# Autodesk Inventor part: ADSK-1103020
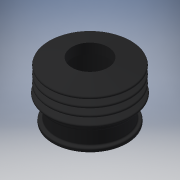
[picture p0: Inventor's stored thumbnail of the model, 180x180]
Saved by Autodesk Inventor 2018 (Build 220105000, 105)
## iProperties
Shininess: 50.0
Length Units: 11272
Angle Units: 11279
Time Units: 11290
Mass Units: 11286
Length Display Precision: 4
Angle Display Precision: 2
Compacted: True
Created: 2000-09
Part Number: ADSK-1103020
Document SubType Name: Modeling
Description: DUST BOOT
Mass: 0.811722 g
Surface Area: 17.5384 cm^2
Volume: 0.872819 cm^3
Density: 0.93 g/cm^3
Material: Rubber
Appearance: Black
Density: 0.0
Volumn: 0.0
Area: 0.0
PropertySet Name: Model Information
Control State: 0
Master: False
Checked Out: False
Author: Autodesk, Inc.
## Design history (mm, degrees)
sketch "Sketch2"
  geometry: L1 (-7.556, -0.987)-(-7.555, -2.302); L2 (-7.428, -0.26)-(-12.947, -1.655); L3 (-3.726, 0)-(-3.726, -10.16); L4 (-9.439, -1.463)-(-7.556, -0.987); L5 (-6.708, -0.987)-(-6.708, -0.26); L6 (-6.708, -0.987)-(-6.708, -2.302); L7 (-6.708, -2.302)-(-7.555, -2.302); L8 (-6.708, -0.26)-(-7.428, -0.26); L9 (-10.074, -10.258)-(-8.804, -10.257); L10 (-8.804, -10.257)-(-8.806, -7.743); L11 (-8.806, -7.743)-(-9.432, -7.744); L12 (-9.432, -7.744)-(-9.439, -1.463); L13 (-10.074, -10.258)-(-10.072, -11.94); L14 (-10.072, -11.94)-(-11.389, -11.941); L15 (-11.389, -11.941)-(-11.389, -11.14); L16 (-11.389, -11.14)-(-10.659, -11.14); L17 (-10.659, -11.14)-(-10.662, -8.05); L18 (-10.662, -8.05)-(-11.393, -8.051); L19 (-12.947, -1.655)-(-9.718, -2.471); L20 (-9.718, -2.471)-(-12.947, -3.287); L21 (-12.947, -3.287)-(-9.718, -4.103); L22 (-9.718, -4.103)-(-12.947, -4.919); L23 (-12.947, -4.919)-(-9.718, -5.735); L24 (-9.718, -5.735)-(-12.947, -6.551); L25 (-12.947, -6.551)-(-11.394, -7.099); L26 (-11.393, -8.051)-(-11.394, -7.099); L27 (-11.395, -6.159)-(-11.395, -6.146)
  constraints: 54 end point, 15 parallel, 4 perpendicular, 1 collinear, 1 point on line
workaxis "Work Axis1"
node "Revolution1" dims "d0" = 90 deg
node "Fillet1" dims "d1" = 0.254
sketch "Sketch4"
  geometry: C1 r 2.981 at (3.726, 0) reference; C2 r 3.701 at (3.726, 0) reference; 1 further point
extrude "Extrusion2" cut sketch "Sketch4" extent not by distance; stored distance "d7" = 25.4; taper "d8" = 0 deg
body "Solid1"
node "Projected Loop1"
